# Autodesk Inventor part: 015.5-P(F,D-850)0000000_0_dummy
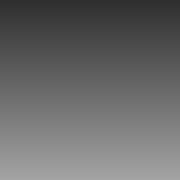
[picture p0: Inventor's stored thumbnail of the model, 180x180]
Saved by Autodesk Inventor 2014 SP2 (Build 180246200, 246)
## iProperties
Created: 2020-01
Part Number: 015.5-P(F,D-850)0000000_0_dummy
Material: Generic
Catalog Web Link: www.cadenas.de
Description: Standard Air Cylinder_dummy-Original Line - Standard Air Cylinders
Vendor: BIMBA
Document SubType Name: Modeling
Designer: psadmin
Manufacturer: BIMBA
Density: 1 g/cm^3
Appearance: PSOLRGB-192-192-192
Category: PARTsolutions
Company: BIMBA
Title: 015.5-P(F,D-850)0000000_0_dummy
Author: Cadenas PARTsolutions
Comments: Original Line - Standard Air Cylinders
PSOL_IDENT_0: {$CADENAS_DATA\23d-libs\bimba\bimba_brand\bimba_imperial\bimba_full_line\original_line_cylinders\sta
PSOL_IDENT_1: ndard_air_cylinders\standard_air_cylinder_dummy.prj},445 {VTYP=3D},{NB=015.5-P(F,D-850)0000000_0_dum
PSOL_IDENT_2: my},{LINA=015.5-P(F,D-850)0000000_0_dummy},{NN=Standard Air Cylinder_dummy},{DATE=23.12.2019 10:36:5
PSOL_IDENT_3: 0},{GEOMDATE=15.10.2019 12:10:06},{VERSION=},{LINEID=30},{WBVAR=STROKE,ACTING,MNT,DER,NR,BM,CO,OO,VO
PSOL_IDENT_4: ,M,EE,EEL,K,Q,Y,F,G,T,B,H,SER,SR,NT,W,E,HL,STPT1,STPT2,STPT3,STPT4,MB,PB,PRC,TB,MN,COLOR,CUSHF,CUSHR
PSOL_IDENT_5: ,FNUT,STRED,ROD,FCD,RCD,BCD,ZHJ},{WBNUMERIC=STROKE,EEL,COLOR,CUSHF,CUSHR,FNUT,STRED,FCD,RCD,BCD,ZHJ}
PSOL_IDENT_6: {NB=015.5-P(F,D-850)0000000_0_dummy},{LINA=015.5-P(F,D-850)0000000_0_dummy},{KT=DUMMY},{PN=015.5-P
PSOL_IDENT_7: (F,D-850)00000},{DASH=-},{BORE=0.43750000},{BOREPN=01},{STROKE=5.500},{STROKEALG=[0.001:50/0.001]},{
PSOL_IDENT_8: STROKE1=5.500},{ACTING=},{ACTINGALG= '' , 'Single' , 'R' , 'Reverse Single' , 'D' , 'Double' },{ACTI
PSOL_IDENT_9: NGPN=},{MNT=P},{MNTALG= '' , 'Front Nose Mounting' , 'P' , 'Rear Pivot Mounting' , 'BF' , 'Front Blo
PSOL_IDENT_10: ck Mounting' , 'BR' , 'Rear Block Mounting for Vertical Positioning' , 'BFT' , 'Front Block Trunnion
PSOL_IDENT_11: Mounting' , 'BRT' , 'Rear Block Trunnion Mounting' },{TYPE=},{MNTPN=P},{DER=},{DERALG= '' , 'N/A' }
PSOL_IDENT_12: ,{NR=},{NRALG= '' , 'Standard' , 'NR' , 'Non-rotating - Hexagon Rod' },{NRPN=},{BM=},{BMALG= '' , 'N
PSOL_IDENT_13: /A' },{BMPN=},{CO=},{COALG= '' , 'N/A' },{OO=},{OOALG= '', 'N/A' },{OOPN=},{VO=Z},{VOALG= 'Z' , 'N/A'
PSOL_IDENT_14: },{VOPN=},{M=},{MALG= '', 'Without Magnet', 'M', 'With Magnet' },{EE=},{EEL=0.000},{EEMAX=44.5000},
PSOL_IDENT_15: {EEALG= '', 'Without Extra Extension', 'EE', 'With Extra Extension' },{EELALG=0},{EEPN=},{EEPN1=0.00
PSOL_IDENT_16: 0},{K=},{KALG= '', 'Standard' , 'K' , 'Ports Rotated 90deg' },{KPN=},{Q=},{QALG= '' , 'Without Side
PSOL_IDENT_17: Ported Rear Head' , 'Q' , 'With Side Ported Rear Head' },{QPN=},{Y=},{YALG= '' , 'Without Pivot Bush
PSOL_IDENT_18: ing' , 'Y' , 'With Pivot Bushing' },{YPN=},{YCON=},{F=},{FALG= '', 'Standard', 'F', 'Molycoated Body'
PSOL_IDENT_19: },{FPN=},{G=},{GPN=},{T=},{TALG= '' , 'Standard' , 'N' , 'Low Temperature' , 'V' , 'High Temperatur
PSOL_IDENT_20: e' },{NPN=},{VPN=},{B=},{BALG= '', 'Without Bumper' , 'B' , 'With Bumper' },{BPN=},{H=},{HALG= '', '
PSOL_IDENT_21: N/A' },{HPN=},{SER=},{SERALG= '' , 'N/A' },{SR=},{SRALG= 'C' , 'Carbon Steel Rod' , 'SR' , '303 Stai
PSOL_IDENT_22: nless Steel Rod' , '' , '303 Stainless Steel Rod1' },{SRPN=},{SRCON=0},{NT=},{NTPN=},{W=},{WALG= ''
PSOL_IDENT_23: , 'N/A' },{WPN=},{E=},{EALG= '' , 'Without Special Lube and Seals' , 'E' , 'With Special Lube and Se
PSOL_IDENT_24: als' },{EPN=},{HL=},{HLALG= '' , 'N/A' },{ST=},{STALG= '' , 'N/A' },{STPT1=},{STPT1ALG= '' , 'N/A' }
PSOL_IDENT_25: ,{STPT2=},{STPT2ALG= '' , 'N/A' },{STPT3=},{STPT3ALG= '' , 'N/A' },{STPT4=},{STPT4ALG= '' , 'N/A' },
PSOL_IDENT_26: {STPN=},{MB=},{MBALG= '' , 'N/A' },{MBPN=},{MBPNALL=},{MBPNALLREAR=},{MBCONF=},{MBCONR=},{FBCON=},{P
PSOL_IDENT_27: B=},{PBALG= '' , 'Without Pivot Bracket' , 'D-780' , 'With D-780' },{PBPN=},{PBPNALL=D-780},{PRC=F,D
PSOL_IDENT_28: -850},{PRCALG= '' , 'Without Pivot Rod Clevis' , 'F,D-850' , 'D-850 (front)' },{PRCPN=(F,D-850)},{PR
PSOL_IDENT_29: CPNALL=D-850},{PRCCONF=1},{PRCCONR=},{TB=},{TBALG= '' , 'N/A' },{TBPN=},{TBPNALL=},{MN=},{MNALG= ''
PSOL_IDENT_30: , 'Without Mounting Nut' , 'F,D-801' , 'D-801 (front)' , 'R,D-154' , 'D-154 (rear)', '2xZ' , 'D-801
PSOL_IDENT_31: (front) & D-154 (rear)' },{MNPN=},{MNCONF=},{MNCONR=},{COLOR=0},{TLEN=10.8620},{FRAC=12.0900},{RGCON=
PSOL_IDENT_32: },{RGDACCON=},{RHCON=P},{RHCON1=P},{RHCONON=1},{RHACCON=},{FNUTCON=0},{RNUTCON=0},{FNUTPN=D-801},{RN
PSOL_IDENT_33: UTPN=D-154},{FNUTTRANS=0.0000},{RNUTTRANS=0.0000},{VHOLECON=2},{A1=0.6880},{A1N=0.6880},{A1P=1.1880}
PSOL_IDENT_34: ,{A1B=1.1880},{A4=0.2500},{A4N=0.2500},{A4P=0.1880},{A5=0.0200},{A1H=1.188},{A1NH=0.5000},{A1PH=1.18
PSOL_IDENT_35: 80},{A1BH=0.8120},{A1SH=0.0000},{A2H=0.1880},{A2NH=0.1880},{LENGTH=1.7500},{LENGTH1=1.7500},{LENGTH2=
PSOL_IDENT_36: 2.6100},{MUL=10.3400},{MUL11=10.3400},{MUL22=15.84},{MUL33=10.3400},{MUL2=0.9400},{MUL211=0.9400},{M
PSOL_IDENT_37: UL222=1.4400},{MUL233=0.9400},{SSS=11.0000},{RGLEN=0.4580},{RHLEN=0.7700},{SSS1=11.0000},{A13=0.9380
PSOL_IDENT_38: },{G5=0.0000},{ON=0},{BADD=0.0000},{MADD=0.0000},{NVADD=0.0000},{TRACKL=10.5520},{TRACKCON=D-74168},
PSOL_IDENT_39: {TRIMCON=0},{TRIMCON1=0},{PINCON=D-787},{FSPACE=0.4833},{SPACE=0.0571},{TEXT=0.1000},{S1=0.7500},{D1=
PSOL_IDENT_40: 0.4840},{D1N=0.4840},{D1B=0.7380},{D1P=0.0000},{FA=0.560},{RA=0.6900},{D1RH=0.7380},{D1NRH=0.4855},{
PSOL_IDENT_41: D1PRH=0.7380},{D1BRH=0.4855},{XT2=0.3800},{BOZO=1.000},{H1=0.0000},{COUTS=0.000},{CUSHF=0},{CUSHR=0}
PSOL_IDENT_42: ,{BUSHCON=D-8597},{CSCON=-},{RHROT=0},{RGROT=0},{HADD=0.000},{DEFL=0.0000},{HEXL=0.0000},{SSADD=0.00
PSOL_IDENT_43: 00},{WFL=0.0000},{FNUT=0},{FBON=0},{STDNUTF=0},{STDNUTR=0},{STRED=0.000},{BORE2ADD=0.0000},{RODTRANS=
PSOL_IDENT_44: 0.00000},{PRCB=0.12000},{PRCL2=0.37500},{PRCTRANS=0.00000},{ROD=},{A2=0.31300},{A2N=0.31300},{A2P=0.
PSOL_IDENT_45: 37500},{FCD=0.000},{RCD=0.000},{BCD=0.000},{ZHJ=0.000}
NN: Standard Air Cylinder_dummy
NT: Standard
NB: 015.5-P(F,D-850)0000000_0_dummy
NBSYN: $PN.$COLOR.$FNUT._$STRED._dummy
LINA: 015.5-P(F,D-850)0000000_0_dummy
PN: 015.5-P(F,D-850)00000
BORE: 0
BOREPN: 01
STROKE: 5.5
ACTING: Single
MNT: Rear Pivot Mounting
DER: N/A
NR: Standard
BM: N/A
CO: N/A
OO: N/A
VO: N/A
M: Without Magnet
EE: Without Extra Extension
EEL: 0
K: Standard
Q: Without Side Ported Rear Head
Y: Without Pivot Bushing
F: Standard
G: Without Magnalube Lubrication
T: Standard
B: Without Bumper
H: N/A
SER: N/A
SR: 303 Stainless Steel Rod1
W: N/A
E: Without Special Lube and Seals
HL: N/A
STPT1: N/A
STPT2: N/A
STPT3: N/A
STPT4: N/A
MB: N/A
PB: Without Pivot Bracket
PRC: D-850 (front)
TB: N/A
MN: Without Mounting Nut
COLOR: 0
A1N: 0.688
A1P: 1.188
A1B: 1.188
A4N: 0.25
A4P: 0.188
A5: 0.02
A1NH: 0.5
A1PH: 1.188
A1BH: 0.812
A1SH: 0
A2NH: 0.188
A13: 0.938
G5: 0
TEXT: 0.1
S1: 0.75
D1N: 0.484
D1B: 0.738
D1P: 0
D1NRH: 0.4855
D1PRH: 0.738
D1BRH: 0.4855
XT2: 0.38
CUSHF: 0
CUSHR: 0
BUSHCON: D-8597
CSCON: -
FNUT: 0
STRED: 0
ROD: Rod
A2N: 0.313
A2P: 0.375
FCD: 0
RCD: 0
BCD: 0
ZHJ: 0
SUPPLIER: BIMBA
ARTICLENO: 015.5-P(F,D-850)0000000_0_dummy
BOMINFO: 015.5-P(F,D-850)0000000_0_dummy
CREATOR: CADENAS GmbH
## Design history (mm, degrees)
node "dummy_XY"
node "dummy_YZ"
node "dummy_ZX"
node "dummy_X"
node "dummy_Y"
node "dummy_Z"
node "dummy_Center"
